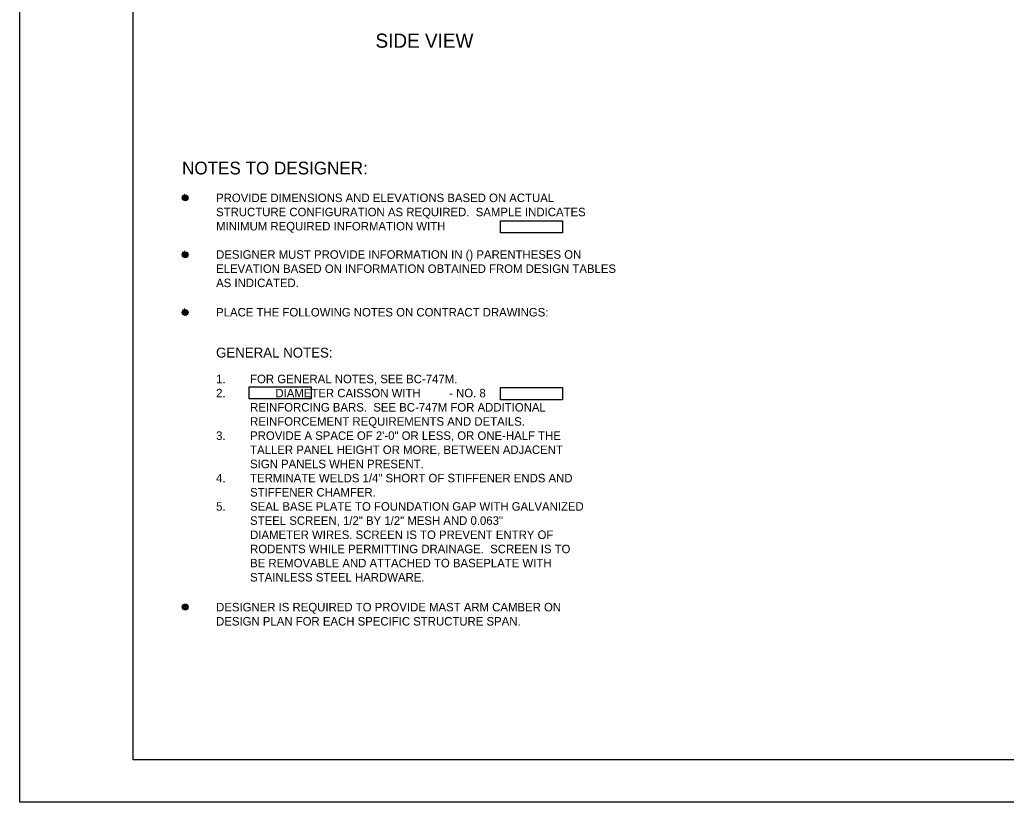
# Model space of a CAD drawing. Extents: x 640117 to 642655, y 297247 to 298435.
# Drawn here: x 640117.5 to 640465.5, y 297247.5 to 297523.7 of the extents above; entities that cross this region are included whole.
import ezdxf

# ---------------------------------------------------------------- set-up
doc = ezdxf.new("R2010")
doc.units = 0
for name, color, linetype in [('10', 7, 'Continuous'), ('2', 7, 'Continuous'), ('53', 7, 'Continuous'), ('PLT-BNDY', 7, 'Continuous')]:
    doc.layers.add(name, color=color, linetype=linetype)

msp = doc.modelspace()

# ---------------------------------------------------------------- linework, layer by layer
at = {"layer": '2'}
for p, q in [((640157.46, 297262.46), (640157.46, 297826.46)), ((640943.46, 297262.46), (640157.46, 297262.46))]:
    msp.add_line(p, q, dxfattribs=at)
for points in [[(640287.08, 297452.69), (640308.97, 297452.69), (640308.97, 297448.38), (640287.08, 297448.38)], [(640198.35, 297394.1), (640220.24, 297394.1), (640220.24, 297389.79), (640198.35, 297389.79)], [(640287.08, 297393.84), (640308.97, 297393.84), (640308.97, 297389.53), (640287.08, 297389.53)]]:
    msp.add_lwpolyline(points, close=True, dxfattribs=at)
for centre, radius in [((640175.85, 297460.79), 1.04), ((640175.85, 297460.79), 0.781), ((640175.85, 297460.79), 0.521), ((640175.85, 297460.79), 0.26), ((640175.85, 297460.79), 0.00000208), ((640175.85, 297440.71), 1.04), ((640175.85, 297440.71), 0.781), ((640175.85, 297440.71), 0.521), ((640175.85, 297440.71), 0.26), ((640175.85, 297440.71), 0.00000208), ((640175.85, 297420.34), 1.04), ((640175.85, 297420.34), 0.781), ((640175.85, 297420.34), 0.521), ((640175.85, 297420.34), 0.26), ((640175.85, 297420.34), 0.00000208), ((640175.85, 297316.39), 1.04), ((640175.85, 297316.39), 0.781), ((640175.85, 297316.39), 0.521), ((640175.85, 297316.39), 0.26), ((640175.85, 297316.39), 0.00000208)]:
    msp.add_circle(centre, radius, dxfattribs=at)
at = {"layer": 'PLT-BNDY'}
msp.add_lwpolyline([(640117.46, 297841.46), (640958.46, 297841.46), (640958.46, 297247.46), (640117.46, 297247.46)], close=True, dxfattribs=at)

# ---------------------------------------------------------------- texts
at = {"layer": '10'}
msp.add_text('NOTES TO DESIGNER:', height=4.5, dxfattribs=at).set_placement((640174.73, 297469.05))
at = {"layer": '53'}
for s, height, p in [('SIDE VIEW', 5, (640242.96, 297513.76)), ('*', 3, (640174.73, 297459.29)), ('PROVIDE DIMENSIONS AND ELEVATIONS BASED ON ACTUAL ', 3, (640186.73, 297459.29)), ('STRUCTURE CONFIGURATION AS REQUIRED.  SAMPLE INDICATES ', 3, (640186.73, 297454.29)), ('MINIMUM REQUIRED INFORMATION WITH', 3, (640186.73, 297449.29)), ('*', 3, (640174.73, 297439.29)), ('DESIGNER MUST PROVIDE INFORMATION IN () PARENTHESES ON ', 3, (640186.73, 297439.29)), ('ELEVATION BASED ON INFORMATION OBTAINED FROM DESIGN TABLES ', 3, (640186.73, 297434.28)), ('AS INDICATED.', 3, (640186.73, 297429.28)), ('*', 3, (640174.73, 297418.92)), ('PLACE THE FOLLOWING NOTES ON CONTRACT DRAWINGS: ', 3, (640186.73, 297418.92)), ('GENERAL NOTES:', 3.5, (640186.73, 297404.41)), ('1.', 3, (640186.73, 297395.37)), ('FOR GENERAL NOTES, SEE BC-747M.', 3, (640198.73, 297395.37)), ('2.', 3, (640186.73, 297390.37)), ('        DIAMETER CAISSON WITH         - NO. 8 ', 3, (640198.73, 297390.37)), ('REINFORCING BARS.  SEE BC-747M FOR ADDITIONAL ', 3, (640198.73, 297385.37)), ('REINFORCEMENT REQUIREMENTS AND DETAILS.', 3, (640198.73, 297380.37)), ('3.', 3, (640186.73, 297375.37)), ('PROVIDE A SPACE OF 2\'-0" OR LESS, OR ONE-HALF THE ', 3, (640198.73, 297375.37)), ('TALLER PANEL HEIGHT OR MORE, BETWEEN ADJACENT ', 3, (640198.73, 297370.37)), ('SIGN PANELS WHEN PRESENT.', 3, (640198.73, 297365.37)), ('4.', 3, (640186.73, 297360.37)), ('TERMINATE WELDS 1/4" SHORT OF STIFFENER ENDS AND ', 3, (640198.73, 297360.37)), ('STIFFENER CHAMFER.', 3, (640198.73, 297355.37)), ('5.', 3, (640186.73, 297350.37)), ('SEAL BASE PLATE TO FOUNDATION GAP WITH GALVANIZED ', 3, (640198.73, 297350.37)), ('STEEL SCREEN, 1/2" BY 1/2" MESH AND 0.063" ', 3, (640198.73, 297345.37)), ('DIAMETER WIRES. SCREEN IS TO PREVENT ENTRY OF ', 3, (640198.73, 297340.37)), ('RODENTS WHILE PERMITTING DRAINAGE.  SCREEN IS TO ', 3, (640198.73, 297335.37)), ('BE REMOVABLE AND ATTACHED TO BASEPLATE WITH ', 3, (640198.73, 297330.37)), ('STAINLESS STEEL HARDWARE. ', 3, (640198.73, 297325.37)), ('DESIGNER IS REQUIRED TO PROVIDE MAST ARM CAMBER ON ', 3, (640186.73, 297314.83)), ('DESIGN PLAN FOR EACH SPECIFIC STRUCTURE SPAN. ', 3, (640186.73, 297309.83))]:
    msp.add_text(s, height=height, dxfattribs=at).set_placement(p)

doc.saveas('drawing.dxf')
